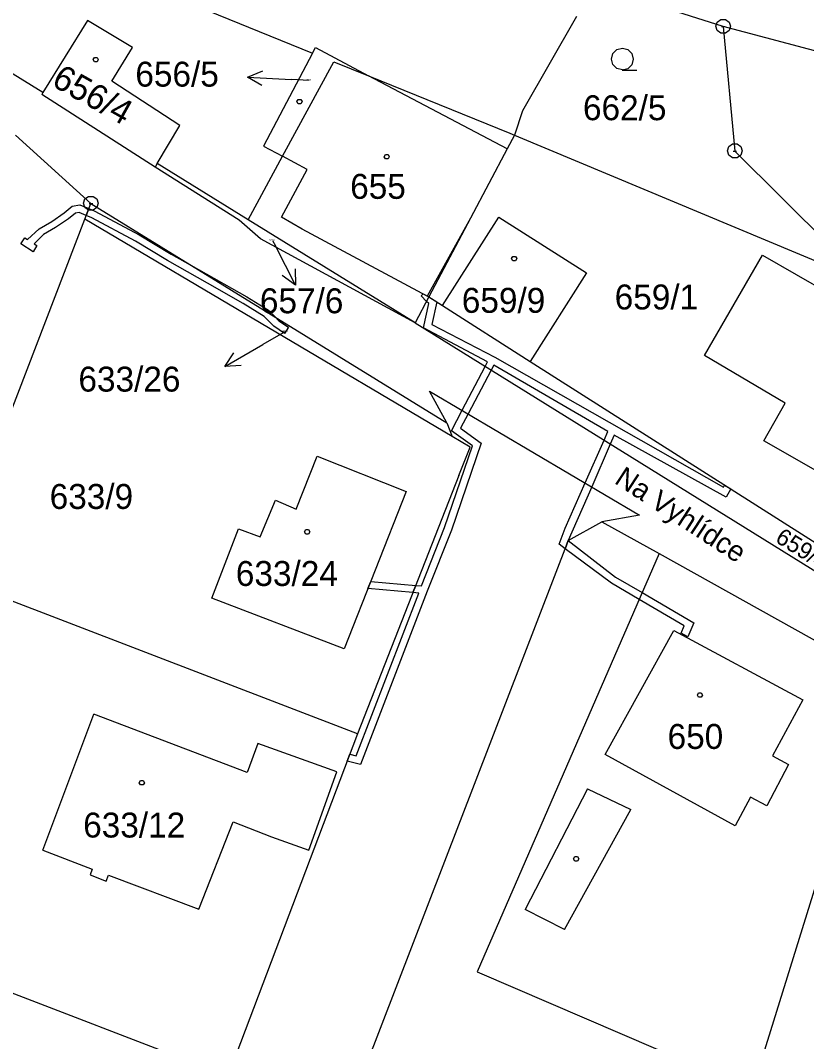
# Model space of a CAD drawing. Extents: x -759060 to -757386, y -1172273 to -1170948.
# Drawn here: x -758121.7 to -758068.1, y -1171249.4 to -1171179.8 of the extents above; entities that cross this region are included whole.
import ezdxf

# ---------------------------------------------------------------- set-up
doc = ezdxf.new("R2010")
doc.units = 0
for name, color, linetype in [('Vrstva 1', 7, 'Continuous'), ('Vrstva 12', 7, 'Continuous'), ('Vrstva 13', 7, 'Continuous'), ('Vrstva 2', 7, 'Continuous'), ('Vrstva 3', 7, 'Continuous'), ('Vrstva 4', 7, 'Continuous'), ('Vrstva 5', 7, 'Continuous'), ('Vrstva 7', 7, 'Continuous'), ('Vrstva 8', 7, 'Continuous')]:
    doc.layers.add(name, color=color, linetype=linetype)

msp = doc.modelspace()

# ---------------------------------------------------------------- linework, layer by layer
at = {"layer": 'Vrstva 1'}
for p, q in [((-758137.64, -1171167.47), (-758101.79, -1171182.04)), ((-758073.81, -1171180.23), (-758083.28, -1171177.22)), ((-758083.81, -1171179.54), (-758087.48, -1171185.97)), ((-758117.13, -1171179.82), (-758120.17, -1171184.74)), ((-758114.07, -1171181.66), (-758117.13, -1171179.82)), ((-758052.54, -1171185.89), (-758073.81, -1171180.23)), ((-758073.81, -1171180.23), (-758073.01, -1171188.72)), ((-758115.48, -1171183.96), (-758114.07, -1171181.66)), ((-758101.79, -1171182.04), (-758105.13, -1171188.38)), ((-758101.79, -1171182.04), (-758101.58, -1171181.67)), ((-758101.58, -1171181.67), (-758097.97, -1171183.6)), ((-758120.17, -1171184.74), (-758123.67, -1171182.58)), ((-758103.83, -1171189.07), (-758100.35, -1171182.63)), ((-758100.35, -1171182.63), (-758097.97, -1171183.6)), ((-758097.97, -1171183.6), (-758088.35, -1171187.51)), ((-758110.84, -1171186.97), (-758115.48, -1171183.96)), ((-758120.17, -1171184.74), (-758120.24, -1171184.86)), ((-758112.51, -1171189.81), (-758120.24, -1171184.86)), ((-758087.48, -1171185.97), (-758088.03, -1171187.64)), ((-758112.37, -1171189.57), (-758110.84, -1171186.97)), ((-758122.03, -1171187.65), (-758116.89, -1171192.29)), ((-758088.03, -1171187.64), (-758088.52, -1171188.57)), ((-758088.35, -1171187.51), (-758088.03, -1171187.64)), ((-758088.03, -1171187.64), (-758064.07, -1171197.64)), ((-758105.13, -1171188.38), (-758103.83, -1171189.07)), ((-758088.52, -1171188.57), (-758091.03, -1171193.3)), ((-758106.17, -1171193.4), (-758103.83, -1171189.07)), ((-758073.01, -1171188.72), (-758064.07, -1171197.64)), ((-758112.37, -1171189.57), (-758112.51, -1171189.81)), ((-758106.8, -1171193.44), (-758112.51, -1171189.81)), ((-758106.17, -1171193.4), (-758112.37, -1171189.57)), ((-758117.31, -1171193.37), (-758116.89, -1171192.29)), ((-758116.89, -1171192.29), (-758092.63, -1171207.24)), ((-758126.67, -1171217.73), (-758117.31, -1171193.37)), ((-758092.27, -1171208.19), (-758117.31, -1171193.37)), ((-758105.34, -1171194.7), (-758106.8, -1171193.44)), ((-758094.79, -1171200.44), (-758106.17, -1171193.4)), ((-758091.03, -1171193.3), (-758093.86, -1171198.67)), ((-758092.94, -1171199.25), (-758089.1, -1171193.22)), ((-758089.1, -1171193.22), (-758083.13, -1171197.03)), ((-758094.79, -1171200.44), (-758105.34, -1171194.7)), ((-758075.09, -1171202.67), (-758071.12, -1171195.82)), ((-758071.12, -1171195.82), (-758057.65, -1171203.61)), ((-758083.13, -1171197.03), (-758086.97, -1171203.06)), ((-758093.86, -1171198.67), (-758094.79, -1171200.44)), ((-758093.86, -1171198.67), (-758092.94, -1171199.25)), ((-758092.94, -1171199.25), (-758086.97, -1171203.06)), ((-758094.79, -1171200.44), (-758062.71, -1171220.37)), ((-758086.97, -1171203.06), (-758062, -1171218.94)), ((-758069.58, -1171205.9), (-758075.09, -1171202.67)), ((-758092.63, -1171207.24), (-758093.82, -1171205.08)), ((-758093.82, -1171205.08), (-758079.51, -1171213.54)), ((-758071.03, -1171208.48), (-758069.58, -1171205.9)), ((-758092.63, -1171207.24), (-758092.27, -1171208.19)), ((-758091.06, -1171208.9), (-758092.27, -1171208.19)), ((-758063.1, -1171213.04), (-758071.03, -1171208.48)), ((-758091.83, -1171210.85), (-758091.06, -1171208.9)), ((-758102.91, -1171213.13), (-758101.48, -1171209.53)), ((-758101.48, -1171209.53), (-758095.41, -1171211.94)), ((-758091.83, -1171210.85), (-758098.72, -1171228.44)), ((-758095.41, -1171211.94), (-758099.64, -1171222.65)), ((-758105.37, -1171215.02), (-758104.32, -1171212.53)), ((-758104.32, -1171212.53), (-758102.91, -1171213.13)), ((-758079.51, -1171213.54), (-758082.08, -1171214)), ((-758084.37, -1171215.28), (-758082.08, -1171214)), ((-758082.08, -1171214), (-758078.18, -1171216.15)), ((-758108.66, -1171219.2), (-758106.83, -1171214.48)), ((-758106.83, -1171214.48), (-758105.37, -1171215.02)), ((-758084.37, -1171215.28), (-758099.2, -1171253.75)), ((-758078.18, -1171216.15), (-758090.57, -1171244.68)), ((-758078.18, -1171216.15), (-758066.56, -1171222.64)), ((-758098.72, -1171228.44), (-758126.67, -1171217.73)), ((-758099.64, -1171222.65), (-758108.66, -1171219.2)), ((-758071.82, -1171252.72), (-758063.29, -1171225.21)), ((-758120.17, -1171236.39), (-758116.69, -1171227.11)), ((-758106.24, -1171231.08), (-758116.69, -1171227.11)), ((-758098.72, -1171228.44), (-758107.56, -1171251.77)), ((-758105.53, -1171229.11), (-758106.24, -1171231.08)), ((-758100.13, -1171231.04), (-758105.53, -1171229.11)), ((-758102.05, -1171236.39), (-758100.13, -1171231.04)), ((-758109.53, -1171240.41), (-758107.21, -1171234.46)), ((-758107.21, -1171234.46), (-758104.6, -1171235.48)), ((-758104.6, -1171235.48), (-758102.05, -1171236.39)), ((-758120.17, -1171236.39), (-758116.8, -1171237.67)), ((-758116.8, -1171237.67), (-758116.95, -1171238.07)), ((-758116.95, -1171238.07), (-758115.85, -1171238.49)), ((-758115.85, -1171238.49), (-758115.69, -1171238.08)), ((-758115.69, -1171238.08), (-758109.53, -1171240.41)), ((-758107.56, -1171251.77), (-758135.53, -1171241.06)), ((-758090.57, -1171244.68), (-758071.82, -1171252.72))]:
    msp.add_line(p, q, dxfattribs=at)
at = {"layer": 'Vrstva 12'}
for p, q in [((-758117.13, -1171179.82), (-758120.17, -1171184.74)), ((-758114.07, -1171181.66), (-758117.13, -1171179.82)), ((-758115.48, -1171183.96), (-758114.07, -1171181.66)), ((-758101.79, -1171182.04), (-758105.13, -1171188.38)), ((-758101.79, -1171182.04), (-758101.58, -1171181.67)), ((-758101.58, -1171181.67), (-758097.97, -1171183.6)), ((-758088.52, -1171188.57), (-758097.97, -1171183.6)), ((-758110.84, -1171186.97), (-758115.48, -1171183.96)), ((-758120.17, -1171184.74), (-758120.24, -1171184.86)), ((-758112.51, -1171189.81), (-758120.24, -1171184.86)), ((-758112.37, -1171189.57), (-758110.84, -1171186.97)), ((-758105.13, -1171188.38), (-758103.83, -1171189.07)), ((-758088.52, -1171188.57), (-758091.03, -1171193.3)), ((-758102.15, -1171189.97), (-758103.83, -1171189.07)), ((-758112.37, -1171189.57), (-758112.51, -1171189.81)), ((-758103.9, -1171193.23), (-758102.15, -1171189.97)), ((-758102.49, -1171194.05), (-758103.9, -1171193.23)), ((-758091.03, -1171193.3), (-758093.97, -1171198.62)), ((-758092.94, -1171199.25), (-758089.1, -1171193.22)), ((-758089.1, -1171193.22), (-758083.13, -1171197.03)), ((-758093.97, -1171198.62), (-758102.49, -1171194.05)), ((-758075.09, -1171202.67), (-758071.12, -1171195.82)), ((-758071.12, -1171195.82), (-758057.65, -1171203.61)), ((-758083.13, -1171197.03), (-758086.97, -1171203.06)), ((-758092.94, -1171199.25), (-758086.97, -1171203.06)), ((-758069.58, -1171205.9), (-758075.09, -1171202.67)), ((-758071.03, -1171208.48), (-758069.58, -1171205.9)), ((-758063.1, -1171213.04), (-758071.03, -1171208.48)), ((-758102.91, -1171213.13), (-758101.48, -1171209.53)), ((-758101.48, -1171209.53), (-758095.41, -1171211.94)), ((-758095.41, -1171211.94), (-758099.64, -1171222.65)), ((-758105.37, -1171215.02), (-758104.32, -1171212.53)), ((-758104.32, -1171212.53), (-758102.91, -1171213.13)), ((-758108.66, -1171219.2), (-758106.83, -1171214.48)), ((-758106.83, -1171214.48), (-758105.37, -1171215.02)), ((-758099.64, -1171222.65), (-758108.66, -1171219.2)), ((-758081.85, -1171229.86), (-758077.18, -1171221.41)), ((-758077.18, -1171221.41), (-758068.39, -1171226.13)), ((-758068.39, -1171226.13), (-758070.45, -1171229.96)), ((-758120.17, -1171236.39), (-758116.69, -1171227.11)), ((-758106.24, -1171231.08), (-758116.69, -1171227.11)), ((-758105.53, -1171229.11), (-758106.24, -1171231.08)), ((-758100.13, -1171231.04), (-758105.53, -1171229.11)), ((-758073, -1171234.72), (-758081.85, -1171229.86)), ((-758070.45, -1171229.96), (-758069.35, -1171230.55)), ((-758102.05, -1171236.39), (-758100.13, -1171231.04)), ((-758069.35, -1171230.55), (-758070.84, -1171233.36)), ((-758071.95, -1171232.76), (-758073, -1171234.72)), ((-758070.84, -1171233.36), (-758071.95, -1171232.76)), ((-758109.53, -1171240.41), (-758107.21, -1171234.46)), ((-758107.21, -1171234.46), (-758104.6, -1171235.48)), ((-758104.6, -1171235.48), (-758102.05, -1171236.39)), ((-758120.17, -1171236.39), (-758116.8, -1171237.67)), ((-758116.8, -1171237.67), (-758116.95, -1171238.07)), ((-758116.95, -1171238.07), (-758115.85, -1171238.49)), ((-758115.85, -1171238.49), (-758115.69, -1171238.08)), ((-758115.69, -1171238.08), (-758109.53, -1171240.41))]:
    msp.add_line(p, q, dxfattribs=at)
at = {"layer": 'Vrstva 13'}
for p, q in [((-758118.72, -1171192.94), (-758118.17, -1171192.48)), ((-758118.17, -1171192.48), (-758117.64, -1171192.4)), ((-758117.64, -1171192.4), (-758117.03, -1171192.65)), ((-758117.21, -1171193.12), (-758117.03, -1171192.65)), ((-758117.03, -1171192.65), (-758117.21, -1171193.12)), ((-758117.03, -1171192.65), (-758116.62, -1171192.82)), ((-758119.56, -1171193.52), (-758118.72, -1171192.94)), ((-758118.42, -1171193.34), (-758119.3, -1171193.94)), ((-758117.95, -1171192.96), (-758118.42, -1171193.34)), ((-758117.7, -1171192.92), (-758117.95, -1171192.96)), ((-758117.21, -1171193.12), (-758117.7, -1171192.92)), ((-758116.84, -1171193.28), (-758117.21, -1171193.12)), ((-758113.85, -1171194.87), (-758116.84, -1171193.28)), ((-758116.62, -1171192.82), (-758113.61, -1171194.43)), ((-758121.21, -1171194.76), (-758120.42, -1171194.02)), ((-758120.42, -1171194.02), (-758119.56, -1171193.52)), ((-758119.3, -1171193.94), (-758120.12, -1171194.42)), ((-758121.68, -1171195.05), (-758121.41, -1171194.63)), ((-758121.41, -1171194.63), (-758121.21, -1171194.76)), ((-758120.12, -1171194.42), (-758120.77, -1171195.04)), ((-758111.68, -1171196.19), (-758113.85, -1171194.87)), ((-758113.61, -1171194.43), (-758111.42, -1171195.75)), ((-758120.84, -1171195.59), (-758121.68, -1171195.05)), ((-758120.57, -1171195.17), (-758120.84, -1171195.59)), ((-758120.77, -1171195.04), (-758120.57, -1171195.17)), ((-758108.96, -1171197.72), (-758111.68, -1171196.19)), ((-758111.42, -1171195.75), (-758109.57, -1171196.8)), ((-758109.57, -1171196.8), (-758106.26, -1171198.67)), ((-758106.52, -1171199.11), (-758108.96, -1171197.72)), ((-758106.26, -1171198.67), (-758104.79, -1171199.58)), ((-758094.39, -1171198.59), (-758094.26, -1171198.45)), ((-758094.02, -1171198.97), (-758094.39, -1171198.59)), ((-758094.26, -1171198.45), (-758093.86, -1171198.67)), ((-758094.02, -1171198.97), (-758093.86, -1171198.67)), ((-758093.86, -1171198.67), (-758094.02, -1171198.97)), ((-758093.86, -1171199.12), (-758094.02, -1171198.97)), ((-758093.86, -1171198.67), (-758093.33, -1171199.01)), ((-758093.33, -1171199.01), (-758093.67, -1171200.54)), ((-758105.08, -1171199.99), (-758106.52, -1171199.11)), ((-758104.79, -1171199.58), (-758104.37, -1171200.01)), ((-758094.24, -1171200.78), (-758093.86, -1171199.12)), ((-758104.42, -1171200.67), (-758105.08, -1171199.99)), ((-758104.37, -1171200.01), (-758104.1, -1171200.29)), ((-758104.1, -1171200.29), (-758103.43, -1171200.73)), ((-758103.71, -1171201.15), (-758104.42, -1171200.67)), ((-758103.43, -1171200.73), (-758103.71, -1171201.15)), ((-758089.87, -1171203.09), (-758094.24, -1171200.78)), ((-758093.67, -1171200.54), (-758089.38, -1171202.78)), ((-758090.03, -1171203.4), (-758089.87, -1171203.09)), ((-758089.38, -1171202.78), (-758073.79, -1171211.63)), ((-758091.6, -1171206.39), (-758090.03, -1171203.4)), ((-758089.61, -1171203.66), (-758091.19, -1171206.64)), ((-758089.43, -1171203.32), (-758089.61, -1171203.66)), ((-758081.67, -1171207.84), (-758089.43, -1171203.32)), ((-758092.33, -1171207.79), (-758091.6, -1171206.39)), ((-758091.19, -1171206.64), (-758091.7, -1171207.61)), ((-758090.89, -1171208.82), (-758092.33, -1171207.79)), ((-758091.7, -1171207.61), (-758090.29, -1171208.64)), ((-758081.93, -1171208.43), (-758081.67, -1171207.84)), ((-758081.23, -1171208.09), (-758081.5, -1171208.7)), ((-758073.61, -1171212.31), (-758081.23, -1171208.09)), ((-758090.29, -1171208.64), (-758092.33, -1171214.56)), ((-758083.22, -1171211.35), (-758081.93, -1171208.43)), ((-758081.5, -1171208.7), (-758082.77, -1171211.61)), ((-758092.79, -1171214.38), (-758090.89, -1171208.82)), ((-758084.58, -1171214.44), (-758083.22, -1171211.35)), ((-758073.79, -1171211.63), (-758073.71, -1171211.49)), ((-758073.71, -1171211.49), (-758073.28, -1171211.76)), ((-758082.77, -1171211.61), (-758084.37, -1171215.28)), ((-758073.28, -1171211.76), (-758073.61, -1171212.31)), ((-758094.36, -1171218.37), (-758092.79, -1171214.38)), ((-758092.33, -1171214.56), (-758093.97, -1171218.73)), ((-758084.98, -1171215.53), (-758084.58, -1171214.44)), ((-758084.58, -1171215.83), (-758084.98, -1171215.53)), ((-758084.37, -1171215.28), (-758084.58, -1171215.83)), ((-758084.58, -1171215.83), (-758084.37, -1171215.28)), ((-758084.37, -1171215.28), (-758081.15, -1171217.76)), ((-758081.43, -1171218.18), (-758084.58, -1171215.83)), ((-758081.15, -1171217.76), (-758079.34, -1171218.82)), ((-758098.02, -1171218.54), (-758097.83, -1171218.06)), ((-758094.95, -1171218.82), (-758098.02, -1171218.54)), ((-758097.83, -1171218.06), (-758094.76, -1171218.33)), ((-758094.95, -1171218.82), (-758094.76, -1171218.33)), ((-758094.76, -1171218.33), (-758094.95, -1171218.82)), ((-758094.76, -1171218.33), (-758094.36, -1171218.37)), ((-758079.54, -1171219.29), (-758081.43, -1171218.18)), ((-758098.83, -1171229.95), (-758094.55, -1171218.86)), ((-758093.97, -1171218.73), (-758098.53, -1171230.55)), ((-758094.55, -1171218.86), (-758094.95, -1171218.82)), ((-758079.34, -1171218.82), (-758075.82, -1171220.89)), ((-758076.46, -1171221.09), (-758079.54, -1171219.29)), ((-758076.67, -1171221.59), (-758076.46, -1171221.09)), ((-758075.82, -1171220.89), (-758076.22, -1171221.84)), ((-758076.22, -1171221.84), (-758076.67, -1171221.59)), ((-758099.43, -1171230.32), (-758099.25, -1171229.84)), ((-758098.53, -1171230.55), (-758099.43, -1171230.32)), ((-758099.25, -1171229.84), (-758098.83, -1171229.95))]:
    msp.add_line(p, q, dxfattribs=at)
at = {"layer": 'Vrstva 3'}
msp.add_lwpolyline([(-758080.67, -1171183.19), (-758081.05, -1171183.09), (-758081.32, -1171182.82), (-758081.42, -1171182.45), (-758081.32, -1171182.08), (-758081.05, -1171181.81), (-758080.68, -1171181.71), (-758080.31, -1171181.81), (-758080.04, -1171182.08), (-758079.94, -1171182.46), (-758080.04, -1171182.84), (-758080.31, -1171183.11), (-758080.69, -1171183.21), (-758079.69, -1171183.21)], dxfattribs=at)
at = {"layer": 'Vrstva 4'}
for p, q in [((-758088.52, -1171188.57), (-758097.97, -1171183.6)), ((-758102.15, -1171189.97), (-758103.83, -1171189.07)), ((-758103.9, -1171193.23), (-758102.15, -1171189.97)), ((-758102.49, -1171194.05), (-758103.9, -1171193.23)), ((-758091.03, -1171193.3), (-758093.97, -1171198.62)), ((-758093.97, -1171198.62), (-758102.49, -1171194.05)), ((-758081.85, -1171229.86), (-758077.18, -1171221.41)), ((-758077.18, -1171221.41), (-758068.39, -1171226.13)), ((-758068.39, -1171226.13), (-758070.45, -1171229.96)), ((-758073, -1171234.72), (-758081.85, -1171229.86)), ((-758070.45, -1171229.96), (-758069.35, -1171230.55)), ((-758069.35, -1171230.55), (-758070.84, -1171233.36)), ((-758083.06, -1171232.19), (-758087.31, -1171240.42)), ((-758083.06, -1171232.19), (-758080.1, -1171233.6)), ((-758071.95, -1171232.76), (-758073, -1171234.72)), ((-758070.84, -1171233.36), (-758071.95, -1171232.76)), ((-758084.63, -1171241.8), (-758080.1, -1171233.6)), ((-758084.63, -1171241.8), (-758087.31, -1171240.42))]:
    msp.add_line(p, q, dxfattribs=at)
at = {"layer": 'Vrstva 5'}
for points in [[(-758116.48, -1171182.34), (-758116.39, -1171182.49), (-758116.48, -1171182.64), (-758116.66, -1171182.64), (-758116.75, -1171182.49), (-758116.66, -1171182.34)], [(-758102.59, -1171185.2), (-758102.5, -1171185.35), (-758102.59, -1171185.5), (-758102.77, -1171185.5), (-758102.86, -1171185.35), (-758102.77, -1171185.2)], [(-758096.65, -1171188.96), (-758096.56, -1171189.11), (-758096.65, -1171189.26), (-758096.83, -1171189.26), (-758096.92, -1171189.11), (-758096.83, -1171188.96)], [(-758087.96, -1171195.9), (-758087.87, -1171196.05), (-758087.96, -1171196.2), (-758088.14, -1171196.2), (-758088.23, -1171196.05), (-758088.14, -1171195.9)], [(-758102.06, -1171214.53), (-758101.97, -1171214.68), (-758102.06, -1171214.83), (-758102.24, -1171214.83), (-758102.33, -1171214.68), (-758102.24, -1171214.53)], [(-758075.3, -1171225.66), (-758075.21, -1171225.81), (-758075.3, -1171225.96), (-758075.48, -1171225.96), (-758075.57, -1171225.81), (-758075.48, -1171225.66)], [(-758113.33, -1171231.63), (-758113.24, -1171231.78), (-758113.33, -1171231.93), (-758113.51, -1171231.93), (-758113.6, -1171231.78), (-758113.51, -1171231.63)], [(-758083.74, -1171236.82), (-758083.65, -1171236.97), (-758083.74, -1171237.12), (-758083.92, -1171237.12), (-758084.01, -1171236.97), (-758083.92, -1171236.82)]]:
    msp.add_lwpolyline(points, close=True, dxfattribs=at)
at = {"layer": 'Vrstva 7'}
for p, q in [((-758106.216, -1171183.692), (-758103.22, -1171183.85)), ((-758102.02, -1171183.92), (-758103.22, -1171183.85)), ((-758104.52, -1171194.82), (-758104.32, -1171195.19)), ((-758102.963, -1171197.866), (-758104.32, -1171195.19)), ((-758103.63, -1171201.03), (-758105.17, -1171201.92)), ((-758107.769, -1171203.419), (-758105.17, -1171201.92))]:
    msp.add_line(p, q, dxfattribs=at)
for points in [[(-758105.244, -1171184.244), (-758106.216, -1171183.692), (-758105.191, -1171183.245)], [(-758102.969, -1171196.747), (-758102.963, -1171197.866), (-758103.861, -1171197.2)], [(-758106.653, -1171203.352), (-758107.769, -1171203.419), (-758107.152, -1171202.486)]]:
    msp.add_lwpolyline(points, dxfattribs=at)
at = {"layer": 'Vrstva 8'}
for p, q in [((-758073.93, -1171180.23), (-758073.69, -1171180.23)), ((-758073.13, -1171188.72), (-758072.89, -1171188.72)), ((-758117.01, -1171192.29), (-758116.77, -1171192.29))]:
    msp.add_line(p, q, dxfattribs=at)
for points in [[(-758073.66, -1171179.75), (-758073.41, -1171179.93), (-758073.31, -1171180.22), (-758073.41, -1171180.51), (-758073.66, -1171180.69), (-758073.97, -1171180.69), (-758074.22, -1171180.51), (-758074.32, -1171180.22), (-758074.22, -1171179.93), (-758073.97, -1171179.75)], [(-758072.86, -1171188.24), (-758072.61, -1171188.42), (-758072.51, -1171188.71), (-758072.61, -1171189), (-758072.86, -1171189.18), (-758073.17, -1171189.18), (-758073.42, -1171189), (-758073.52, -1171188.71), (-758073.42, -1171188.42), (-758073.17, -1171188.24)], [(-758116.74, -1171191.81), (-758116.49, -1171191.99), (-758116.39, -1171192.28), (-758116.49, -1171192.57), (-758116.74, -1171192.75), (-758117.05, -1171192.75), (-758117.3, -1171192.57), (-758117.4, -1171192.28), (-758117.3, -1171191.99), (-758117.05, -1171191.81)]]:
    msp.add_lwpolyline(points, close=True, dxfattribs=at)

# ---------------------------------------------------------------- texts
at = {"layer": 'Vrstva 2'}
for s, height, rotation, p in [('656/4', 1.7, 330.76854, (-758119.657, -1171184.221)), ('659/4', 1.14, 328.01834, (-758070.329, -1171215.324))]:
    msp.add_text(s, height=height, rotation=rotation, dxfattribs=at).set_placement(p)
for s, height, p in [('656/5', 0.1, (-758102.227, -1171183.92)), ('662/5', 1.7, (-758083.364, -1171186.62)), ('655', 1.7, (-758099.228, -1171191.98)), ('657/6', 0.1, (-758104.722, -1171194.82)), ('659/9', 1.7, (-758091.62, -1171199.75)), ('659/1', 1.7, (-758081.202, -1171199.52)), ('633/26', 0.1, (-758103.887, -1171201.03)), ('633/9', 1.7, (-758119.707, -1171213.12)), ('633/24', 1.7, (-758107.02, -1171218.37)), ('650', 1.7, (-758077.598, -1171229.48)), ('633/12', 1.7, (-758117.422, -1171235.52))]:
    msp.add_text(s, height=height, dxfattribs=at).set_placement(p)
at = {"layer": 'Vrstva 7'}
for s, p in [('656/5', (-758113.867, -1171184.33)), ('657/6', (-758105.38, -1171199.78)), ('633/26', (-758117.748, -1171205.12))]:
    msp.add_text(s, height=1.7, dxfattribs=at).set_placement(p)
msp.add_text('Na Vyhlídce', height=1.4, rotation=326.81513, dxfattribs=at).set_placement((-758081.291, -1171211.325))

doc.saveas('drawing.dxf')
